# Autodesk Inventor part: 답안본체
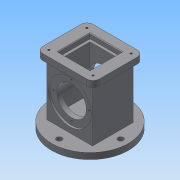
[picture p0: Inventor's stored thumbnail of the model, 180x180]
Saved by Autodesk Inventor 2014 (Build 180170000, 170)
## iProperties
Created: 2018-10
Part Number: 답안본체
Material: 일반
Document SubType Name: Modeling
Designer: NET
Density: 1 g/cm^3
Appearance: 기본값
Author: NET
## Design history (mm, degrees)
sketch "스케치1"
  geometry: L1 (-37, -33)-(37, -33); L2 (37, -33)-(37, 33); L3 (37, 33)-(-37, 33); L4 (-37, 33)-(-37, -33); L5 (-37, -33)-(37, 33); L6 (37, -33)-(-37, 33); 1 further point
  constraints: 12 end point, 2 midpoint, 2 parallel, 1 horizontal, 1 perpendicular
  dimensions: "d0" = 74 distance of L1.start L1.end; "d1" = 66 distance of L1.end L2.end
extrude "돌출1" new body sketch "스케치1" stored distance "d2" = 88; taper "d3" = 0 deg
sketch "스케치2"
  geometry: L1 (-46, -41)-(46, -41); L2 (46, -41)-(46, 41); L3 (46, 41)-(-46, 41); L4 (-46, 41)-(-46, -41); L5 (-46, -41)-(46, 41); L6 (46, -41)-(-46, 41); 1 further point
  constraints: 12 end point, 2 midpoint, 2 parallel, 1 horizontal, 1 perpendicular
  dimensions: "d4" = 82 distance of L1.end L2.end; "d5" = 92 distance of L2.end L3.end
extrude "돌출2" join sketch "스케치2" distance "d6" = 10; taper "d7" = 0 deg
sketch "스케치3"
  geometry: L1 (46, 41)-(46, -41) reference; C1 r 62.5 at (0, 0); 1 further point
  constraints: 1 centre point, 1 coincident
  dimensions: "d8" = 125 diameter of C1
extrude "돌출3" join sketch "스케치3" distance "d9" = 10; taper "d10" = 0 deg
sketch "스케치4"
  geometry: L1 (-26, -26)-(26, -26); L2 (26, -26)-(26, 26); L3 (26, 26)-(-26, 26); L4 (-26, 26)-(-26, -26); L5 (-26, -26)-(26, 26); L6 (26, -26)-(-26, 26); 1 further point
  constraints: 12 end point, 2 midpoint, 2 parallel, 2 perpendicular, 1 horizontal
  dimensions: "d11" = 52 distance of L1.end L2.end
extrude "돌출4" cut sketch "스케치4" distance "d12" = 8; taper "d13" = 0 deg
sketch "스케치5"
  geometry: L1 (-22, -22)-(22, -22); L2 (22, -22)-(22, 22); L3 (22, 22)-(-22, 22); L4 (-22, 22)-(-22, -22); L5 (-22, -22)-(22, 22); L6 (22, -22)-(-22, 22); 1 further point
  constraints: 12 end point, 2 midpoint, 2 parallel, 2 perpendicular, 1 horizontal
  dimensions: "d14" = 44 distance of L1.end L2.end
extrude "돌출5" cut sketch "스케치5" distance "d15" = 74; taper "d16" = 0 deg
sketch "스케치6"
  geometry: L1 (-25.5, -98)-(99.5, -98) reference; C1 r 35 at (37, -44); 1 further point
  constraints: 1 centre point, 1 coincident
  dimensions: "d17" = 70 diameter of C1; "d18" = 54 distance from line of L1 C1.centre
extrude "돌출6" cut sketch "스케치6" distance "d19" = 3; taper "d20" = 0 deg
hole "구멍1" diameter "d23" = 48; stored, may be unused: countersink angle "d27" = 90 deg, drill point angle "d29" = 118 deg; dims "d21" = 10, "d22" = 10, "d24" = 6, "d25" = 4, "d26" = 2, "d28" = 8
fillet "모깎기1" dims "d30" = 10
hole "구멍2" diameter "d33" = 3.242; stored, may be unused: countersink angle "d37" = 90 deg, drill point angle "d39" = 118 deg; dims "d31" = 10, "d32" = 10, "d34" = 4, "d35" = 4, "d36" = 2, "d38" = 6
hole "구멍3" diameter "d42" = 3.242; stored, may be unused: countersink angle "d46" = 90 deg, drill point angle "d48" = 118 deg; dims "d40" = 10, "d41" = 10, "d43" = 4, "d44" = 4, "d45" = 2, "d47" = 6
hole "구멍4" diameter "d51" = 3.242; stored, may be unused: countersink angle "d55" = 90 deg, drill point angle "d57" = 118 deg; dims "d49" = 10, "d50" = 10, "d52" = 4, "d53" = 4, "d54" = 2, "d56" = 6
hole "구멍5" diameter "d60" = 3.242; stored, may be unused: countersink angle "d64" = 90 deg, drill point angle "d66" = 118 deg; dims "d58" = 10, "d59" = 10, "d61" = 4, "d62" = 4, "d63" = 2, "d65" = 6
sketch "스케치7"
  geometry: C1 r 24 at (0, 0) reference; 1 further point
  constraints: 1 vertical alignment
  dimensions: "d67" = 29 distance of C1.centre point (0, 29)
hole "구멍6" sketch "스케치7" at (0, 29) diameter "d68" = 3.242; stored, may be unused: countersink angle "d72" = 90 deg, drill point angle "d74" = 118 deg; dims "d69" = 4, "d70" = 4, "d71" = 2, "d73" = 6
sketch "스케치8"
  geometry: L1 (-62.5, -54)-(62.5, -54) reference; L2 (0, -54)-(0, -36); L3 (0, -54)-(28, -54); L4 (28, -54)-(24.826, -36); L5 (24.826, -36)-(0, -36); 1 further point
  constraints: 8 end point, 1 midpoint, 1 parallel, 1 perpendicular, 1 point on line
  dimensions: "d78" = 18 distance of L2.start L2.end; "d79" = 28 distance of L2.start L3.end; "d80" = 80 deg angle of L1 L4
revolve "회전1" sketch "스케치8" stored, may be unused: angle "d81" = 90 deg
chamfer "모따기1" distance "d82" = 1; stored, may be unused: second distance "d83" = 2, angle "d84" = 45 deg
sketch "스케치9"
  geometry: C1 r 62.5 at (0, 0) reference; 1 further point
  constraints: 1 vertical alignment
  dimensions: "d85" = 50 distance of C1.centre point (0, 50)
hole "구멍7" sketch "스케치9" at (0, 50) diameter "d86" = 9; stored, may be unused: countersink angle "d90" = 90 deg, drill point angle "d92" = 118 deg; dims "d87" = 4, "d88" = 4, "d89" = 2, "d91" = 6
node "솔리드1"
mirror "대칭1"
pattern_circular "원형 패턴1" dims angle "d76" = 360 deg
mirror "대칭2"
pattern_circular "원형 패턴2" dims angle "d94" = 360 deg
